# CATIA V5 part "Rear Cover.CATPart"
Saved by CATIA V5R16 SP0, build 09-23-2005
Part number: Cover.1
Bounding box of the stored display mesh (mm): x -37.982 to 37.982, y 0 to 16, z -37.982 to 37.982
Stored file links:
  C:\V5_education\CATIA Data\ASD\Power Transmission Gear Assembly\Assembly Data\Rear Cover.CATPart
  C:\V5_education\CATIA Data\ASD\Power Transmission Gear Assembly\Assembly Data\Power Transmission Gear Assembly.CATProduct
  C:\V5_education\CATIA Data\ASD\Power Transmission Gear Assembly\Assembly Data\Power Transmission Gear.CATPart
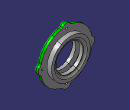
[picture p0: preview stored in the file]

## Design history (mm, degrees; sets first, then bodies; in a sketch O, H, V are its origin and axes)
Set1
  DatumSurface1: linked copy from another document
Set2 "Reference Data"
  Point1 "Center Point": (0, 0, 0)
Body1 (main body)
  Sketch1 on yz-plane, origin (0, 0, 0), H (0, 1, 0), V (0, 0, 1)
    line L1 (0, 0) -> (0, 26)
    line L2 (0, 26) -> (4, 26)
    line L3 (4, 26) -> (4, 34.5)
    line L4 (4, 34.5) -> (10, 34.5)
    line L5 (10, 34.5) -> (10, 26)
    line L6 (10, 26) -> (16, 26)
    line L7 (16, 26) -> (16, 0)
    point P7 (16, 0)
    axis line L8 (0, 0) -> (16, 0)
    distance L8 L2 = 26 {= Sketch1.distance(L6 H)}
    distance L8 L4 = 34.5
    distance L1 L7 = 16
    distance L5 L3 = 6
    distance L5 L7 = 6
    distance L6 H = 26
    vertical: L1 V, L3 V, L5 V, L7 V
    horizontal: L2 H, L4 H, L6 H, L8 H
    coincidence: P7 H
  Shaft1: profile Sketch1, axis Sketch1.L8, angle 360
  Sketch2 on zx-plane, origin (0, 0, 0), H (1, 0, 0), V (0, 0, 1)
    construction circle A1 centre (0, 0) radius 32
    circle A2 centre (0, 32) radius 6
    point P1 (0, 32)
    construction circle A3 centre (0, 0) radius 34.5
    radius A1 = 32
    radius A2 = 6
    radius A3 = 34.5
    coincidence: P1 A1, P1 V
  Pad1: profile Sketch2, direction (0, 1, 0), up to face of Shaft1 from Sketch1.L5, opposite side up to face of Shaft1 from Sketch1.L3
  CircPattern1: of Pad1, instances 4, angular step 90 {= 360.0*1 deg/CircPattern1.AngularNumber}, axis from face of Shaft1 from Sketch1.L4
  Body2
    Sketch3 on yz-plane, origin (0, 0, 0), H (0, 1, 0), V (0, 0, 1)
      point P1 (0, 18)
      line L1 (0, 18) -> (4.2633, 18)
      line L2 (4.2633, 18) -> (5, 24)
      point P3 (5, 24)
      line L3 (5, 24) -> (9, 24)
      point P4 (9, 24)
      line L4 (9, 24) -> (9.7367, 18)
      point P5 (9.7367, 18)
      line L5 (9.7367, 18) -> (14, 18)
      line L6 (14, 18) -> (14, 22)
      line L7 (14, 22) -> (17, 22)
      line L8 (17, 22) -> (17, 0)
      point P9 (17, 0)
      line L9 (0, 18) -> (0, 0)
      axis line L10 (0, 0) -> (17, 0)
      construction line L11 (7, 24) -> (7, 0)
      point P10 (7, 24)
      point P11 (7, 0)
      distance L3 H = 24
      distance L1 H = 18
      angle L2 L4 = 14
      distance L11 L8 = 10
      distance L8 L9 = 17
      distance L7 H = 22
      distance L6 L8 = 3
      distance P4 P3 = 4
      coincidence: P1 V, P5 L1, P9 H, P11 L10
      horizontal: L1 H, L3 H, L5 H, L7 H, L10 H
      vertical: L6 V, L8 V, L9 V, L11 V
      midpoint: P10 L3
      symmetry: P3 P4 L11, L2 L4 L11
    Shaft2: profile Sketch3, axis Sketch3.L10, angle 360
    Fillet1: radius 3, on edge [face of Shaft2 from Sketch3.L6 | face of Shaft2 from Sketch3.L7]
  Remove1: tool Body2
  Fillet2: radius 3, on edge [face of Shaft1 from Sketch1.L4 | face of Pad1 from Sketch2.A2]; edge [face of Pad1 from Sketch2.A2 | face of Shaft1 from Sketch1.L4]; edge [face of CircPattern1 | face of Shaft1 from Sketch1.L4] (x3); edge [face of Shaft1 from Sketch1.L4 | face of CircPattern1] (x3)
  Fillet3: radius 3, on edge [face of CircPattern1 | face of Shaft1 from Sketch1.L4]
  Fillet4: radius 3, on edge [face of Shaft1 from Sketch1.L1 | face of Shaft1 from Sketch1.L2]
  Fillet5: radius 3, on edge [face of Shaft1 from Sketch1.L2 | face of CircPattern1]
  Body3
    Sketch4 on face of Shaft1 from Sketch1.L3, origin (-9.4665, 4, 27.9071), H (1, 0, 0), V (0, 0, 1)
      point P1 (9.4665, 4.0929)
      reference intersected line E1 through (0, -27.9071) direction (-1, 0) from xy-plane
      reference intersected line E2 through (9.4665, 0) direction (0, 1) from yz-plane
      distance P1 E1 = 32
      coincidence: E2 P1
    Hole1: placed by Sketch4, at (0, 4, 32) direction (0, 1, 0), diameter 2.459, depth 10, counterbore diameter 5, counterbore depth 4.4, threaded "M3", thread diameter 3, thread depth 5.6, pitch 0.5
    CircPattern2: of the body so far, instances 4, angular step 90 {= 360.0*1 deg/CircPattern2.AngularNumber}, axis from face of Shaft1 from Sketch1.L4
  Assemble1: tool Body3
  AssyPrtSPLIT1: SplitPlane DatumSurface1, _MechModInactiveResultOUT result of AssyPrtSPLIT1, deactivated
